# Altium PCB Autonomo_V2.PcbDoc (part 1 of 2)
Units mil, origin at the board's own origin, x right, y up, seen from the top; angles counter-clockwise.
Board outline 3937.01 x 3937.01 mil, 4 copper layers (Top Layer, GND, PWR, Bottom Layer), stack 62.204 mil thick; 148 components, 84 nets, 484 pads, 385 vias.
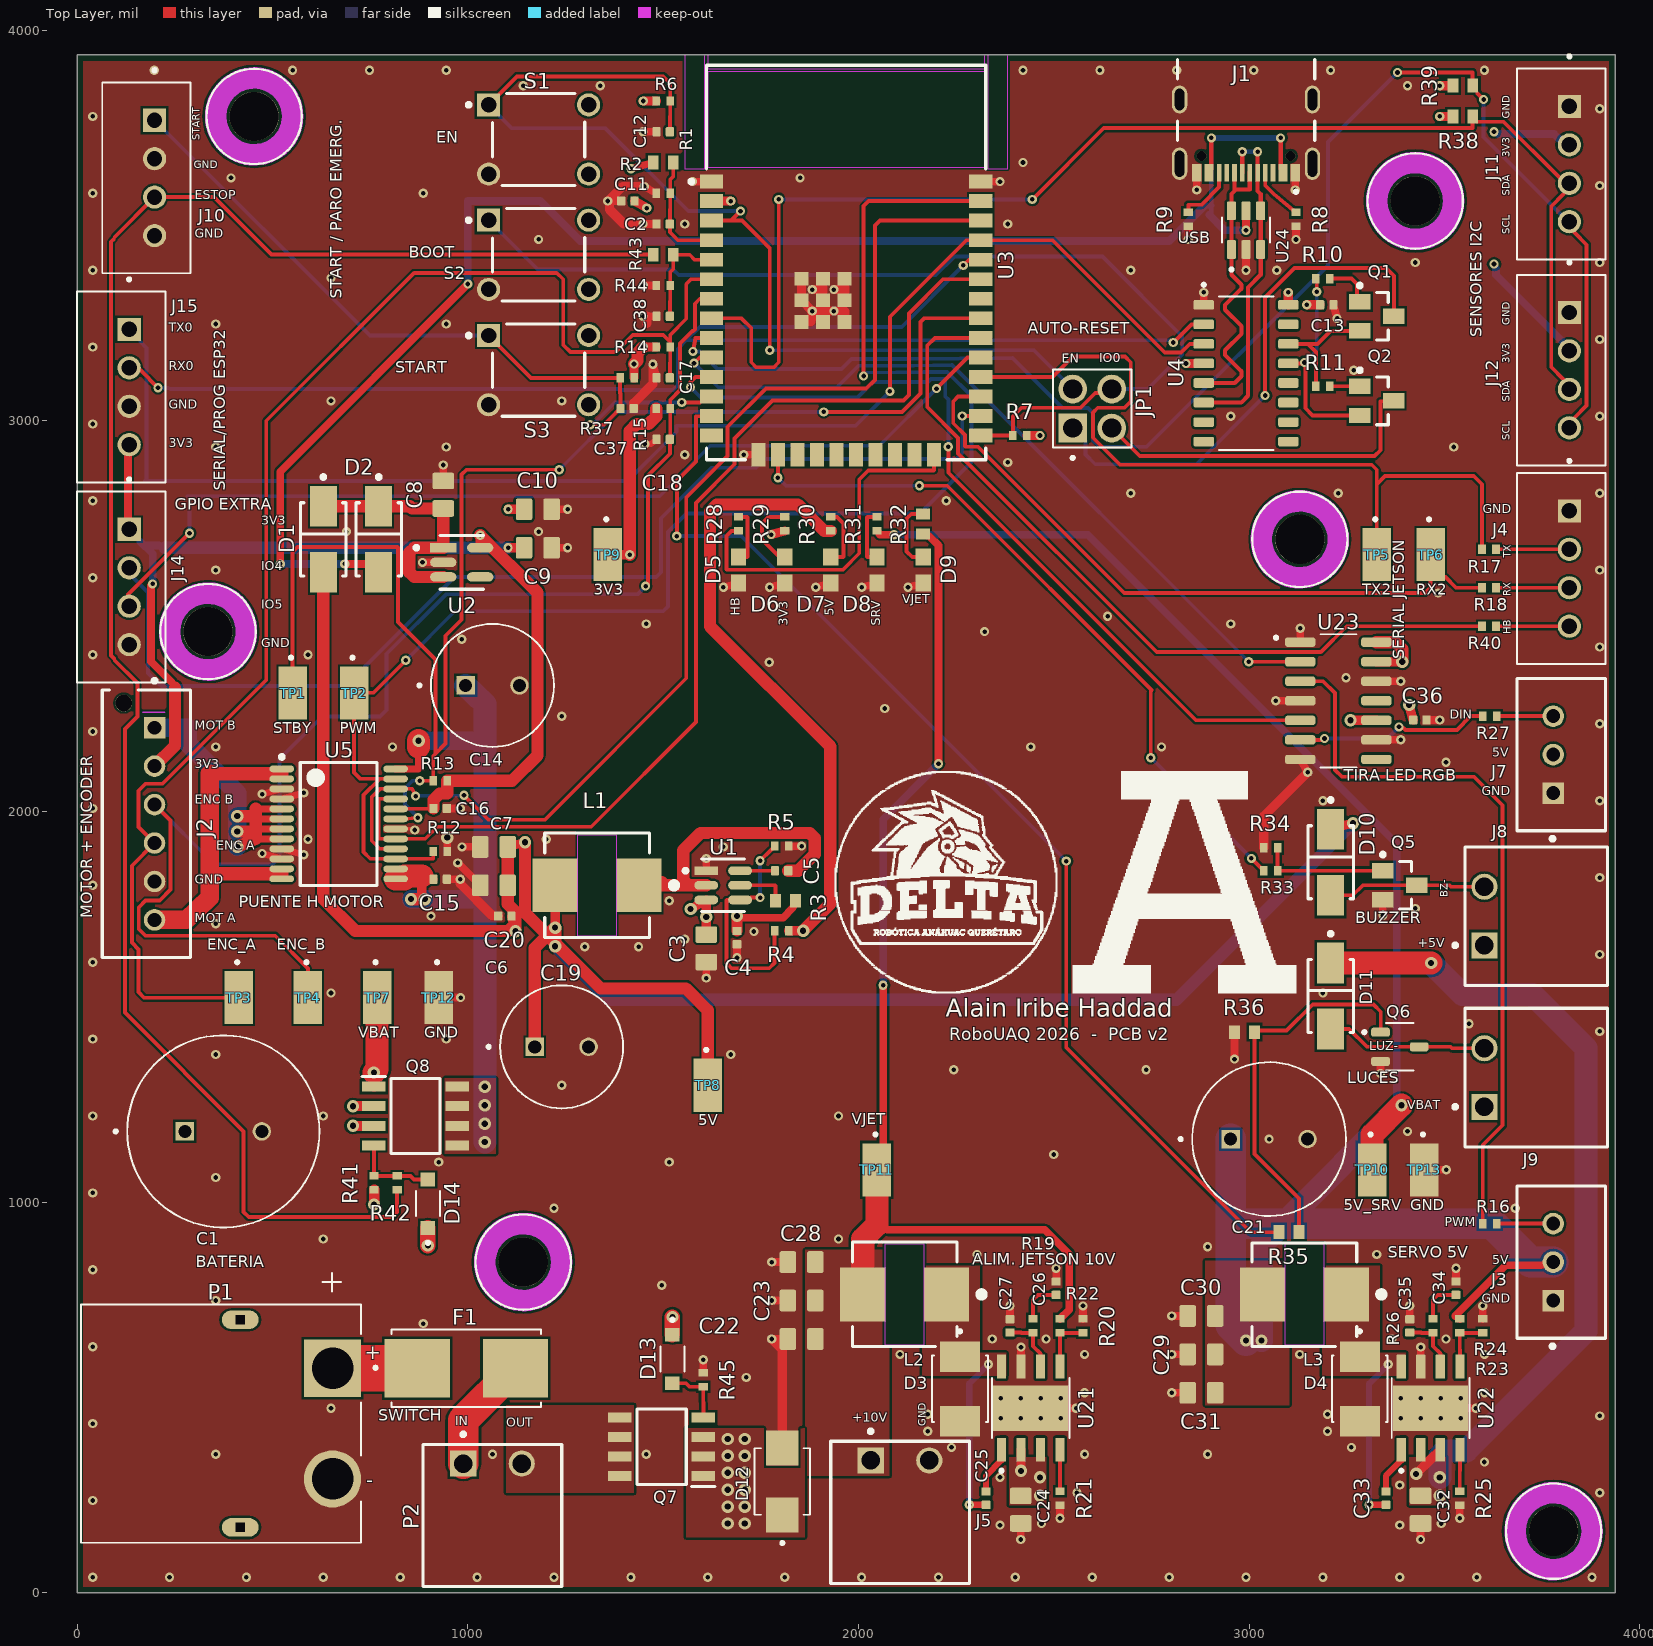
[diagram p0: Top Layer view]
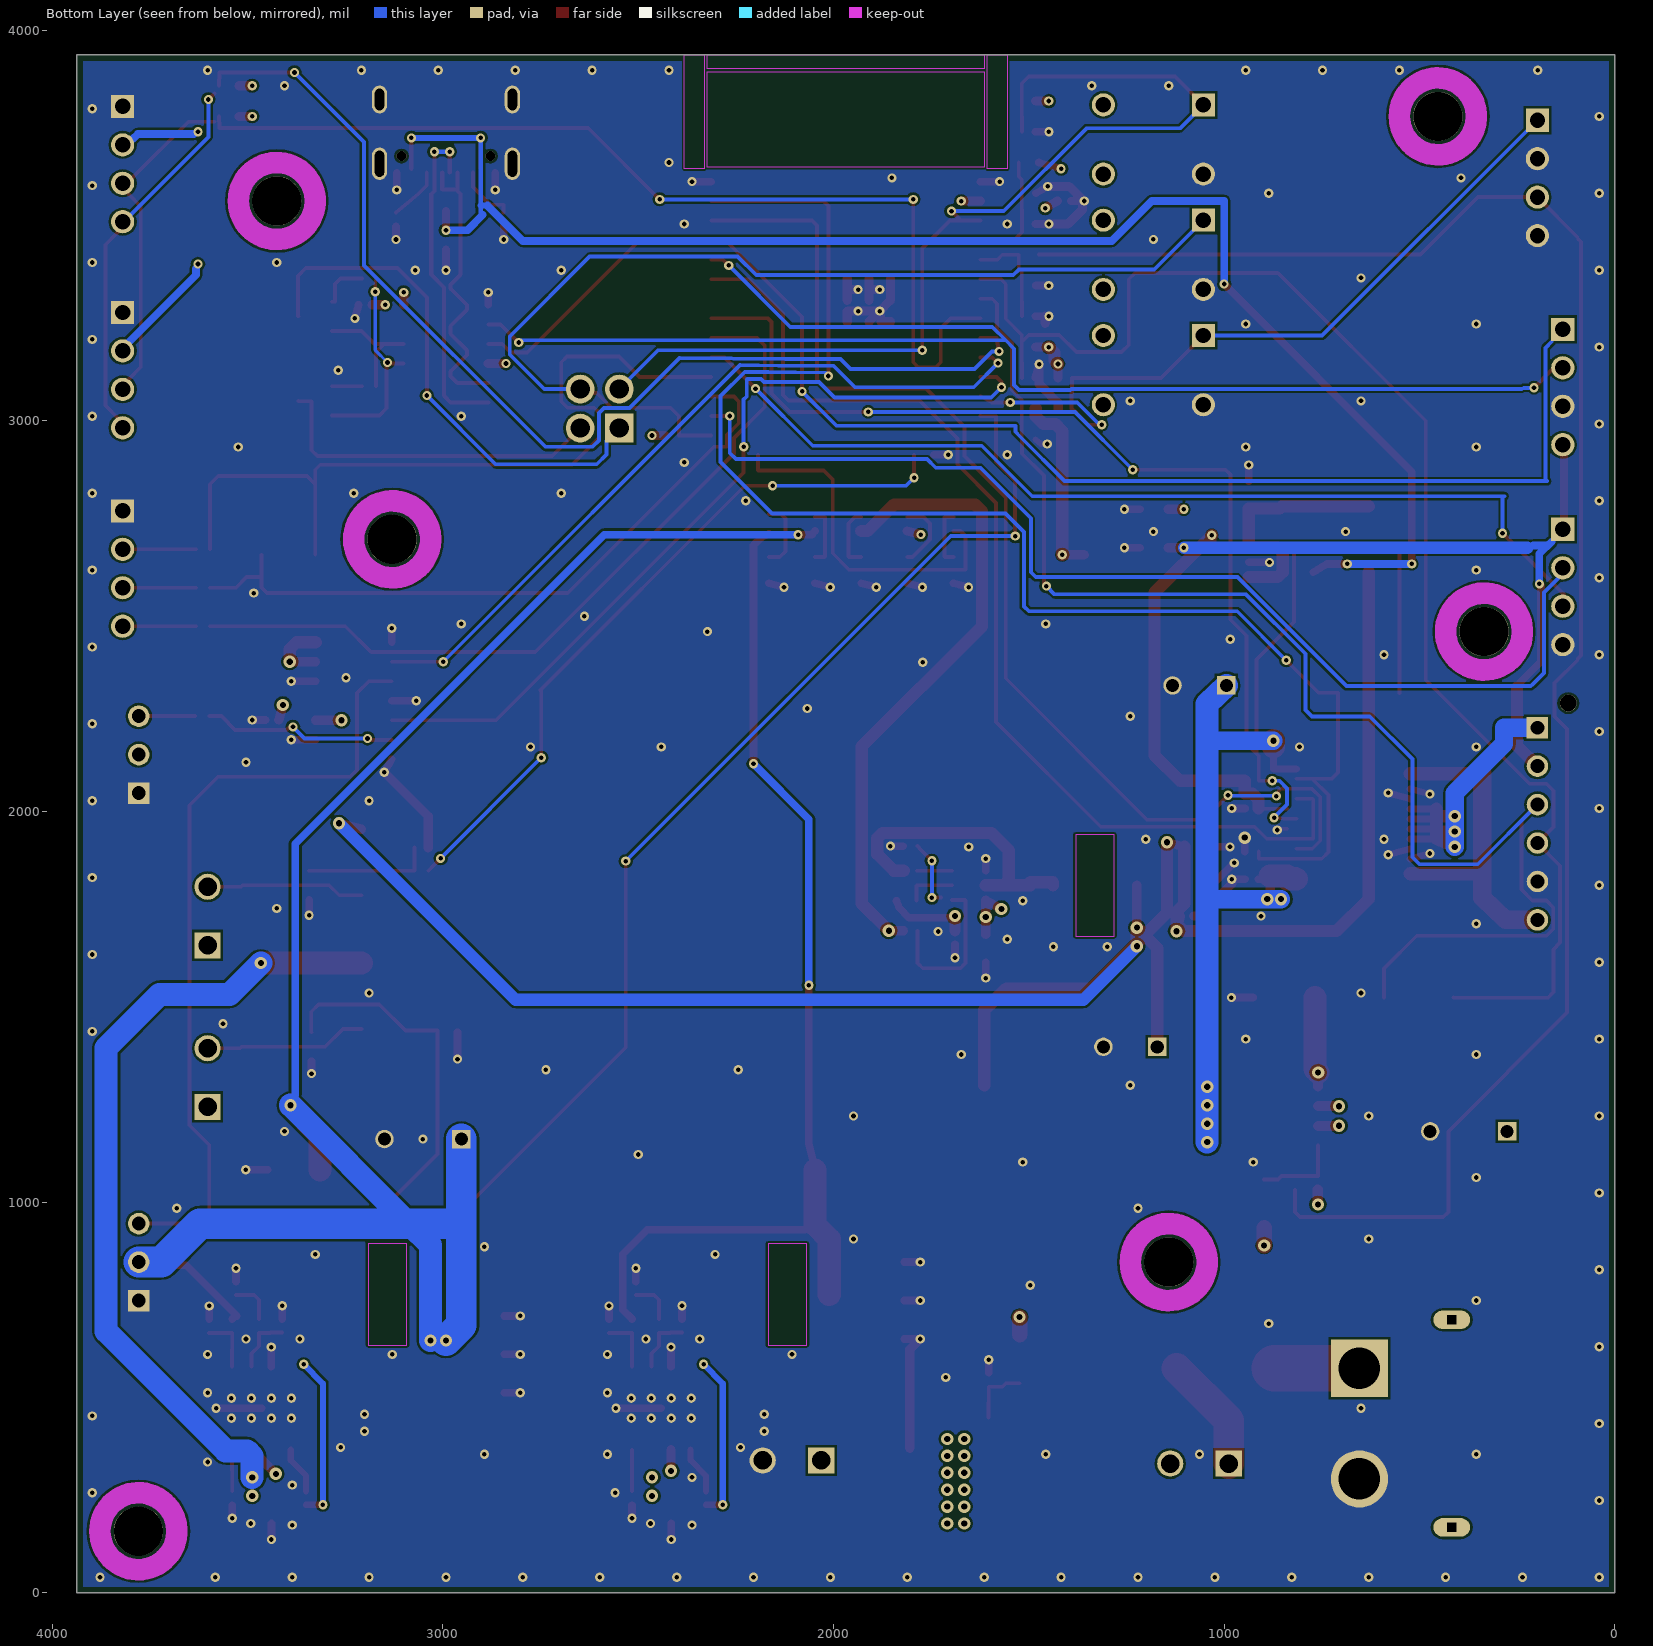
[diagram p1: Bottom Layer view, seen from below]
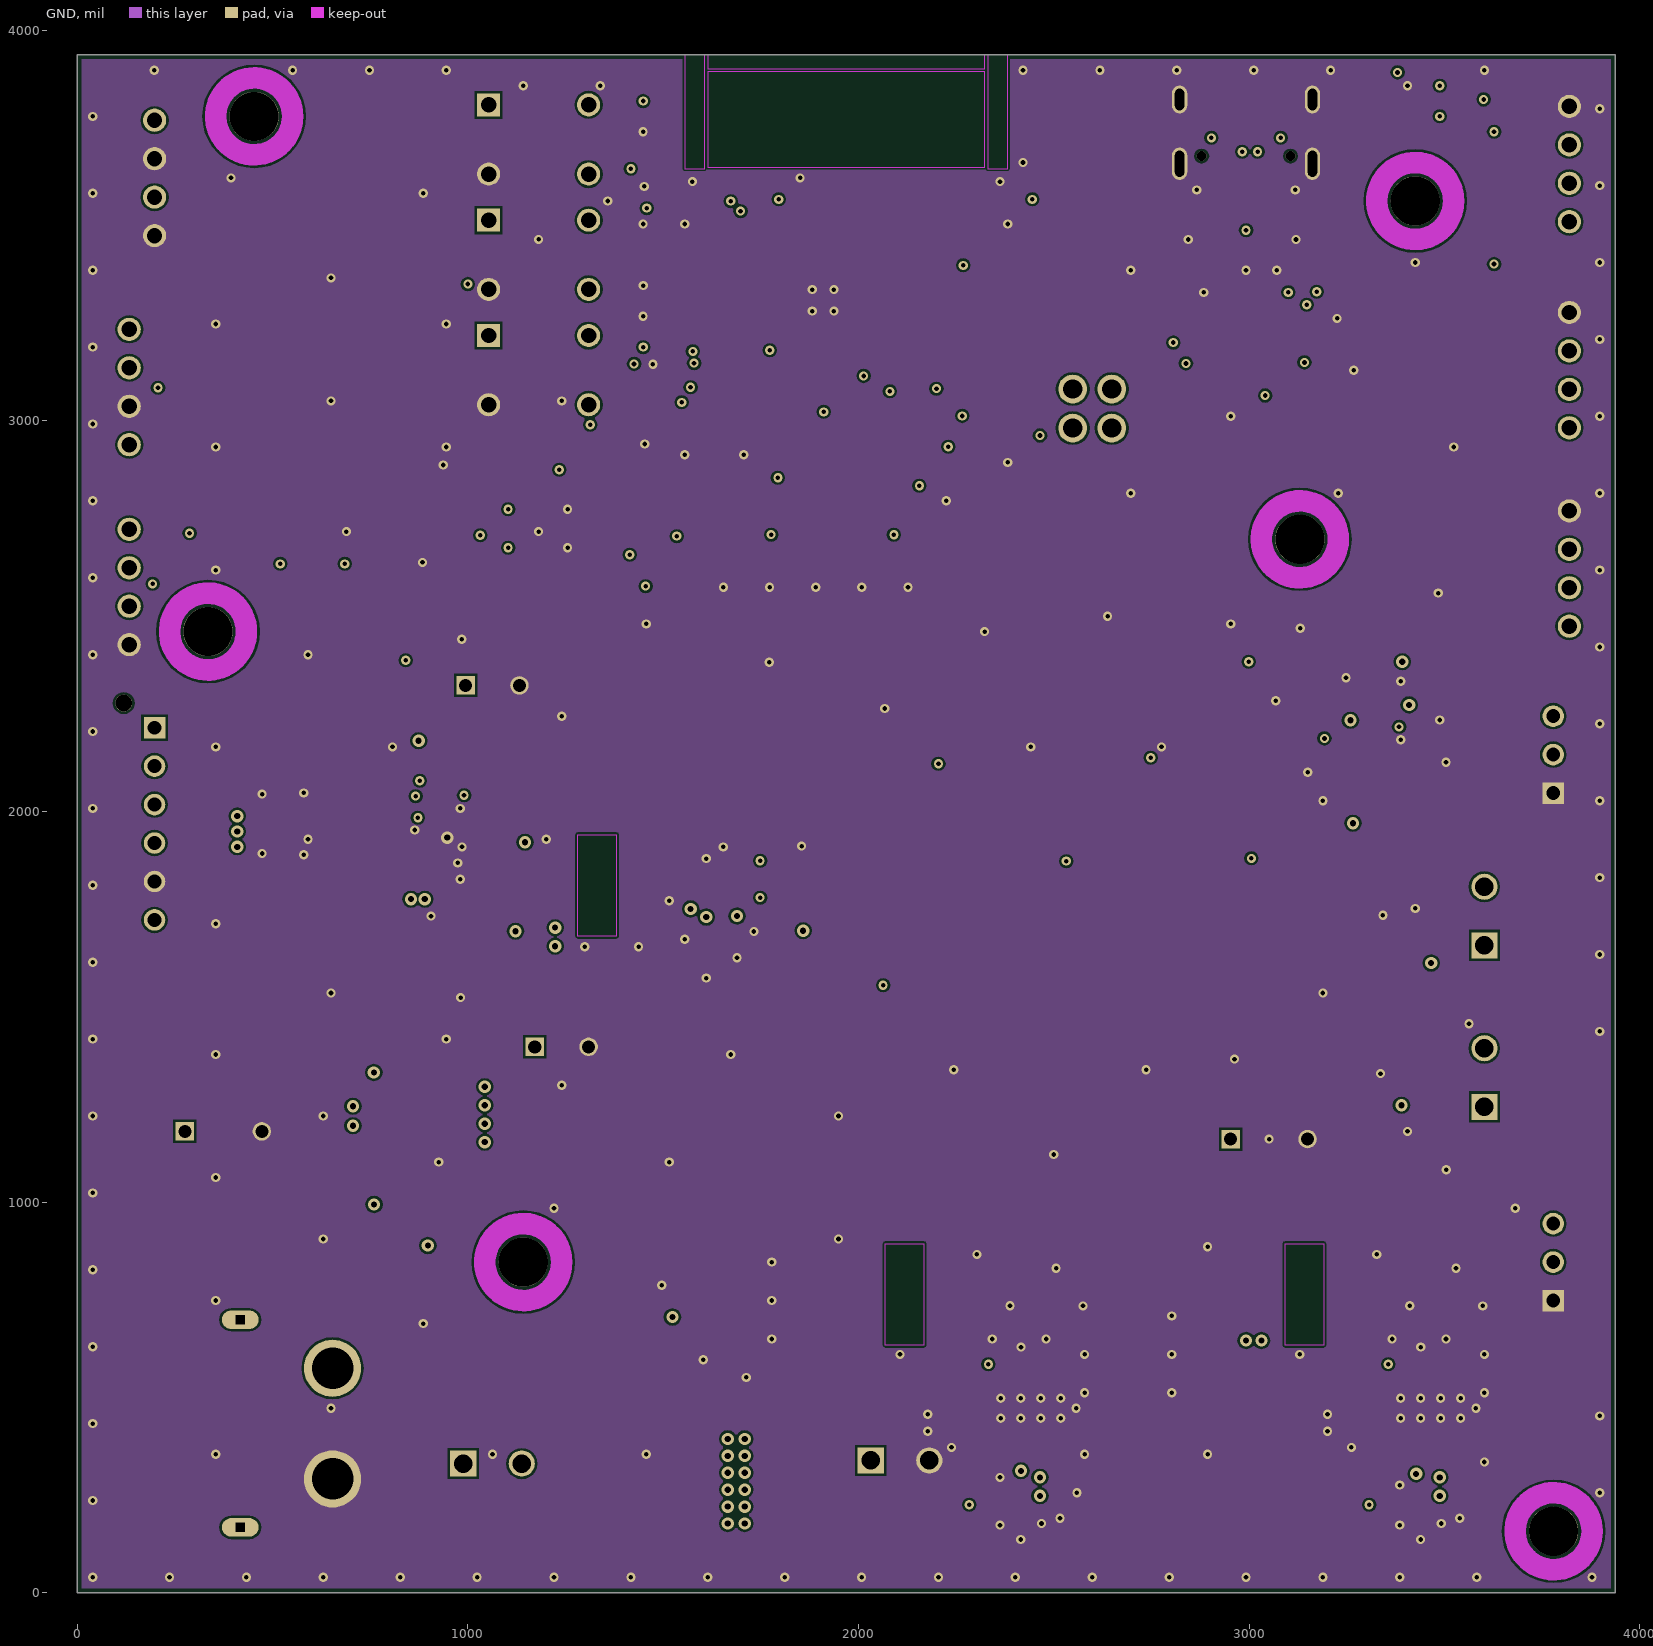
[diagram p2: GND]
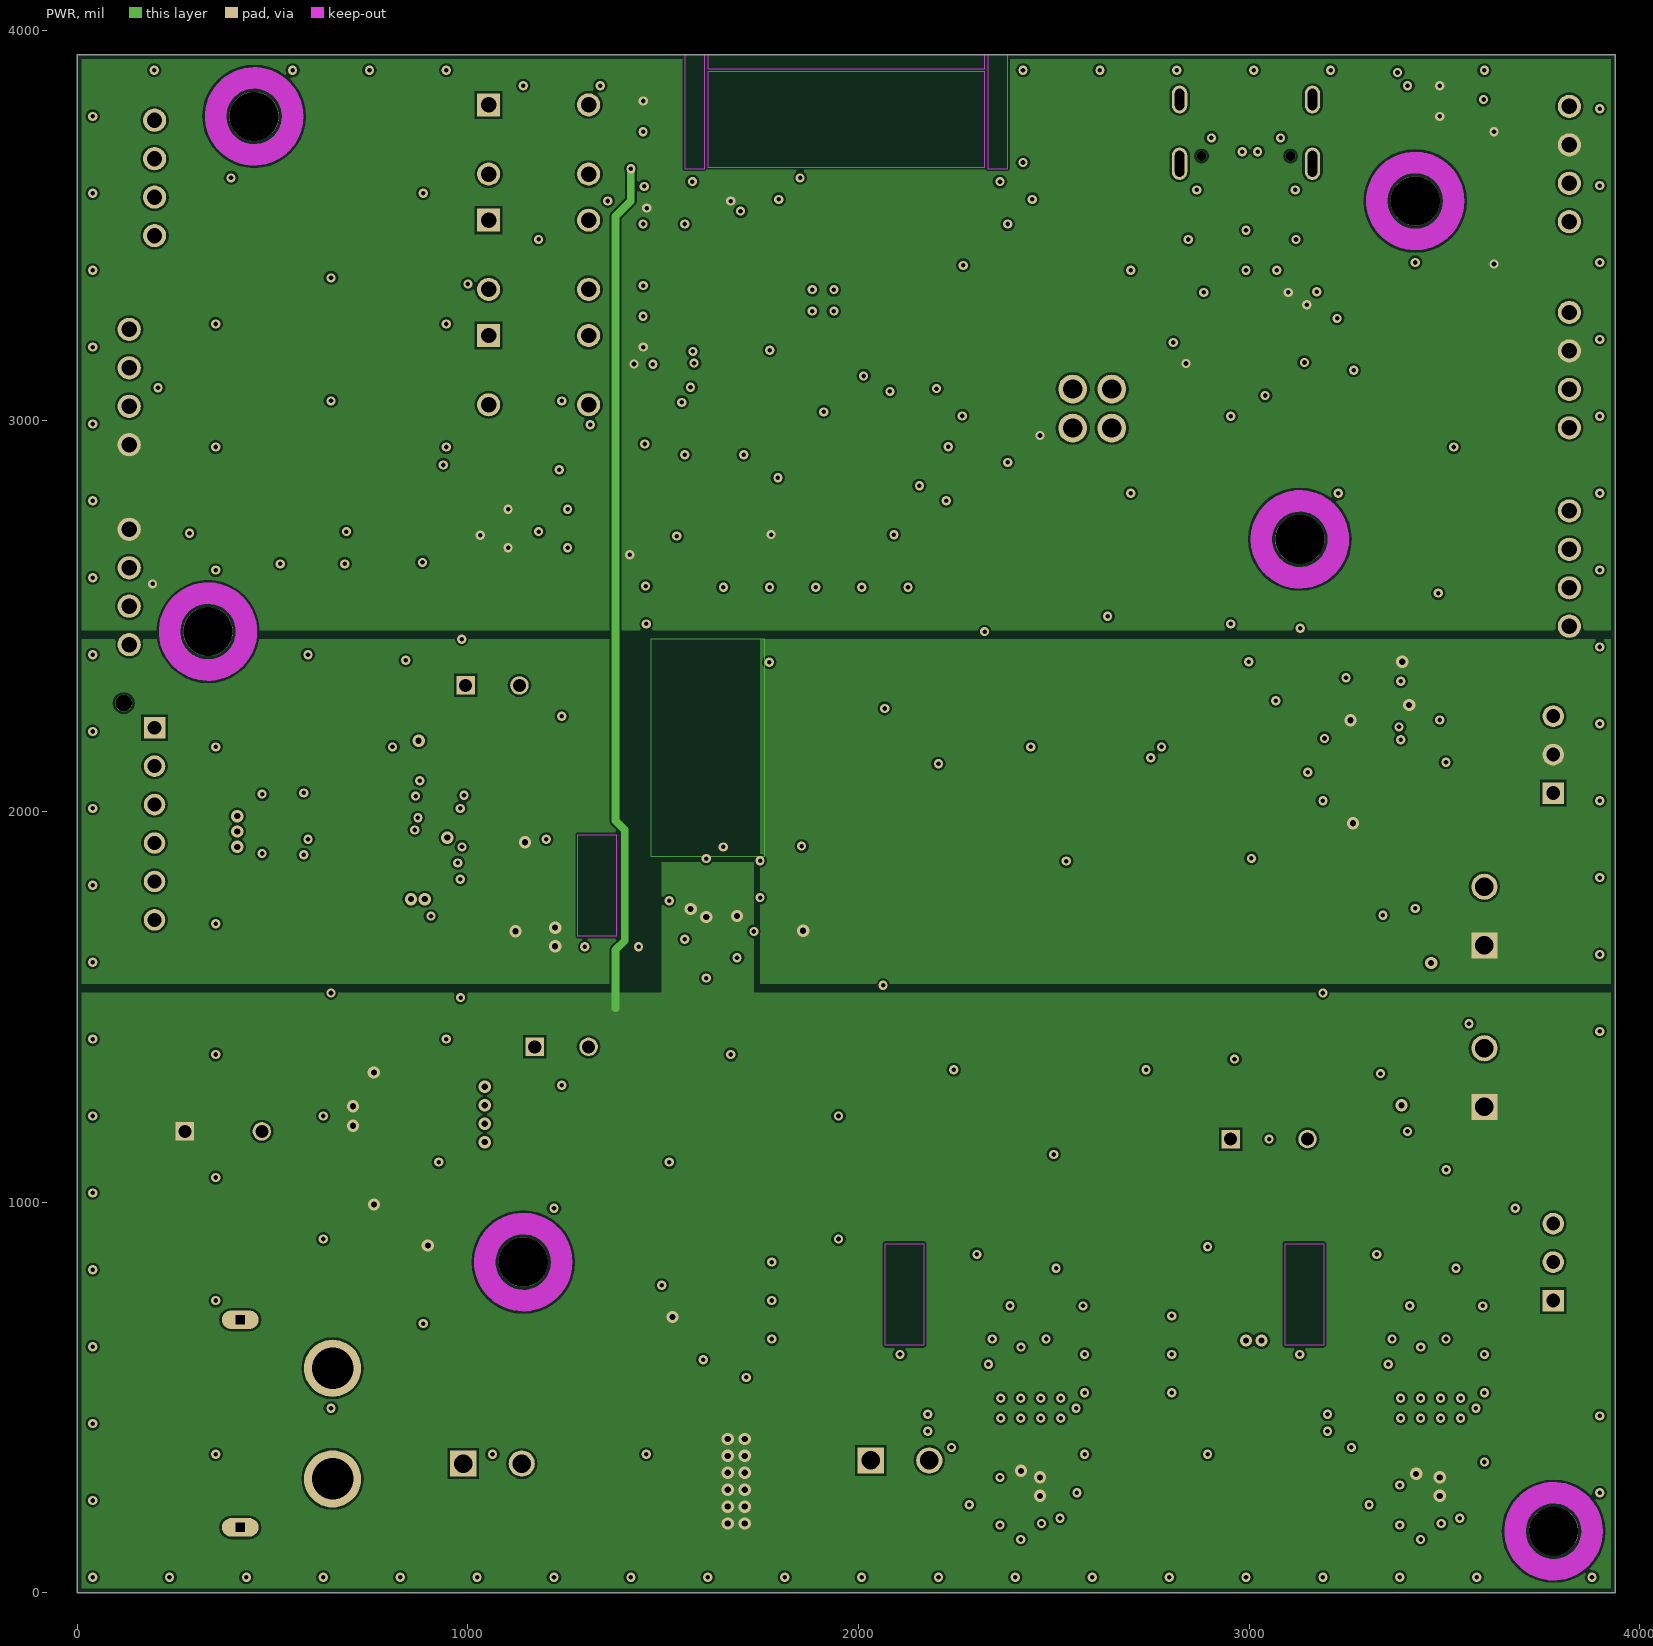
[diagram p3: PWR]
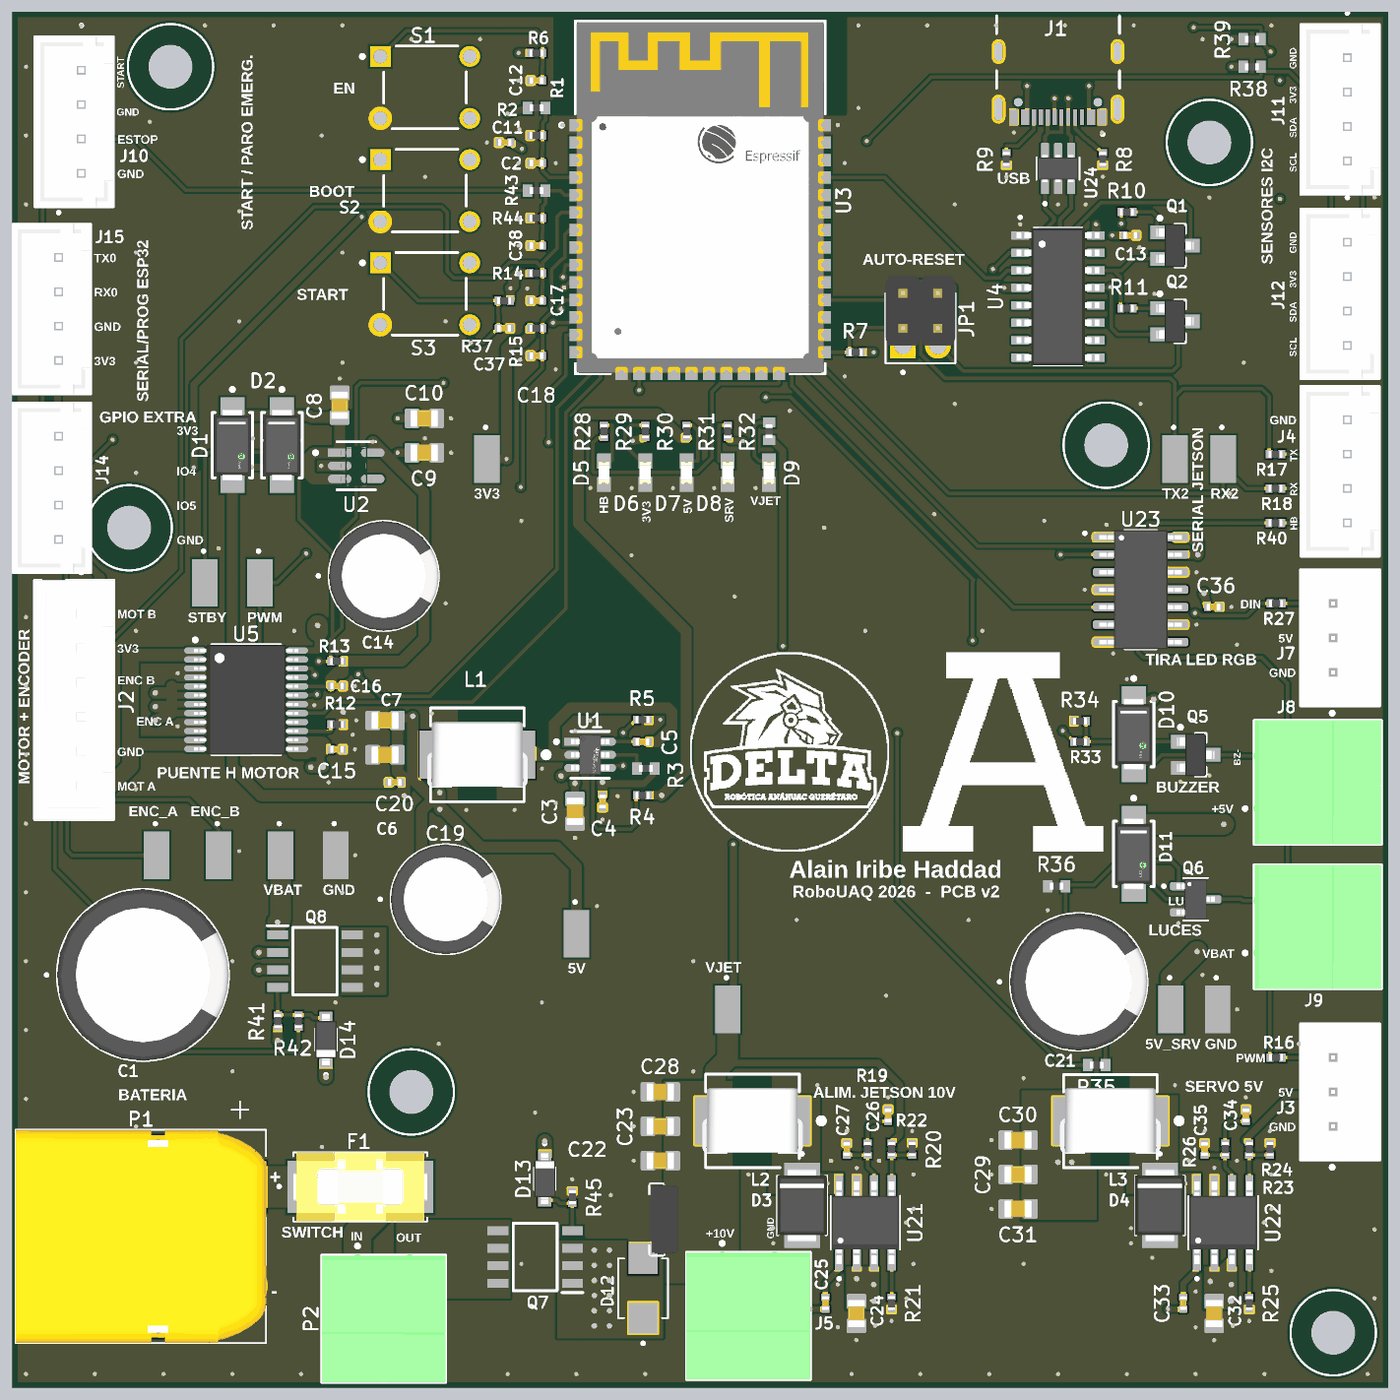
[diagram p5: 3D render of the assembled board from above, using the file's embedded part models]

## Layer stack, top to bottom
Top Solder: solder mask 0.4, Solder Resist, Dk 3.5
Top Layer: signal copper 1.4
Dielectric 2: prepreg 7.874, PP-006, Dk 4.1
GND: signal copper 1.378
Dielectric 1: dielectric 40.9, FR-4, Dk 4.8
PWR: signal copper 1.378
Dielectric 3: prepreg 7.874, PP-006, Dk 4.1
Bottom Layer: signal copper 1.4
Bottom Solder: solder mask 0.4, Solder Resist, Dk 3.5

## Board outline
0,0 0,3937.01 3937.01,3937.01 3937.01,0

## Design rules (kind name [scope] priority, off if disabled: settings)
Clearance C_NeckDown [(InRegionAbsolute(433,1760,906,2177) Or InRegionAbsolute(1520,1703,1787,1919) Or InRegionAbsolute(844,2529,1124,2746) Or InRegionAbsolute(2799,2876,3185,3369) Or InRegionAbsolute(2860,3380,3124,3596) Or InRegionAbsolute(2743,3552,3241,3917) Or InRegionAbsolute(3029,2059,3428,2508) Or InRegionAbsolute(2285,277,2596,669) Or InRegionAbsolute(3309,277,3620,669) Or InRegionAbsolute(1300,227,1692,521) Or InRegionAbsolute(670,1074,1062,1367) Or InRegionAbsolute(2264,197,2350,600) Or InRegionAbsolute(3287,197,3374,600))] p1: gap=5.91 ignorepadtopadclearanceinfootprint=FALSE
Clearance C_PowerHi [InNetClass('POWER_HI')] p2: gap=7.87 ignorepadtopadclearanceinfootprint=FALSE
Clearance [All] p3: gap=5.91 ignorepadtopadclearanceinfootprint=FALSE
DiffPairsRouting [All] p1: maxlimit=6 minlimit=5 mostfreqgap=6 toplayer_mingap=6 toplayer_minwidth=10.95 toplayer_maxwidth=10.95 toplayer_prefwidth=10.95 midlayer1_maxgap=5 midlayer1_prefgap=5 midlayer1_minwidth=4.33 midlayer1_maxwidth=4.33 midlayer1_prefwidth=4.33 midlayer2_maxgap=5 midlayer2_prefgap=5 midlayer2_minwidth=4.33 midlayer2_maxwidth=4.33 midlayer2_prefwidth=4.33 bottomlayer_mingap=6 bottomlayer_minwidth=10.95 bottomlayer_maxwidth=10.95 bottomlayer_prefwidth=10.95 impedanceprofiledriven=TRUE impedanceprofileid={DB9AC6A6-0DAB-40E2-92AF-4522C3993068} impedanceprofilevalue=90.000000 maxuncoupledlength=500
HoleSize [All] p1: absolutevalues=TRUE maxlimit=129.92 minlimit=1 maxpercent=80.000 minpercent=20.000
MinimumSolderMaskSliver Sliver_ESP_EP [InComponent('U3')] p1: minsoldermaskwidth=0
MinimumSolderMaskSliver [All] p2: minsoldermaskwidth=3
PolygonConnect [All] p1: connectstyle=Direct reliefconductorwidth=10 reliefentries=4 polygonreliefangle="90 Angle" airgapwidth=10
RoutingLayers [All] p1: top layer_v5=TRUE mid layer 1_v5=FALSE mid layer 2_v5=FALSE bottom layer_v5=TRUE
RoutingVias V_Power [InNetClass('POWER_HI') Or InNetClass('POWER') Or InNet('GND')] p1: holewidth=15.75 width=31.5 viastyle="Through Hole" minholewidth=11.81 minwidth=23.62 maxholewidth=19.68 maxwidth=39.37
RoutingVias [All] p2: holewidth=11.81 width=23.62 viastyle="Through Hole" minholewidth=11.81 minwidth=23.62 maxholewidth=15.75 maxwidth=31.5
SilkToSilkClearance [All] p1: silktosilkclearance=4
SilkToSolderMaskClearance [IsPad] p1: minsilkscreentomaskgap=4 clearancetoexposedcopper=TRUE
SolderMaskExpansion Tent_Vias [IsVia] p1: expansion=0 istentingtop=TRUE
SolderMaskExpansion [All] p2: expansion=0 istentingtop=FALSE
SupplyNets "Schematic Supply Nets_2" [InNet('+3V3')] p1: voltage=0.000
SupplyNets "Schematic Supply Nets_1" [InNet('+5V')] p2: voltage=0.000
SupplyNets "Schematic Supply Nets" [InNet('GND')] p3: voltage=0.000
Width W_NeckDown [(InRegionAbsolute(433,1760,906,2177) Or InRegionAbsolute(1520,1703,1787,1919) Or InRegionAbsolute(844,2529,1124,2746) Or InRegionAbsolute(2799,2876,3185,3369) Or InRegionAbsolute(2860,3380,3124,3596) Or InRegionAbsolute(2743,3552,3241,3917) Or InRegionAbsolute(3029,2059,3428,2508) Or InRegionAbsolute(2285,277,2596,669) Or InRegionAbsolute(3309,277,3620,669) Or InRegionAbsolute(1300,227,1692,521) Or InRegionAbsolute(670,1074,1062,1367) Or InRegionAbsolute(2264,197,2350,600) Or InRegionAbsolute(3287,197,3374,600))] p1: maxlimit=314.96 minlimit=7.87 preferedwidth=15.75
Width W_USB [InNetClass('USB')] p2: maxlimit=13.78 minlimit=7.87 preferedwidth=10.94
Width W_GND [InNet('GND')] p3: maxlimit=314.96 minlimit=11.81 preferedwidth=23.62
Width W_Power [InNetClass('POWER')] p4: maxlimit=236.22 minlimit=19.68 preferedwidth=31.5
Width W_PowerHi [InNetClass('POWER_HI')] p5: maxlimit=314.96 minlimit=19.68 preferedwidth=59.06
Width [All] p6: maxlimit=39.37 minlimit=5.91 preferedwidth=9.84
24 further rules are at their usual default settings.

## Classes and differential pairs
net class POWER_HI: +5V_SERVO +VJET MOT_A MOT_B NetF1_1 NetF1_2 SW_SERVO SW_VJET VBAT VBAT_MOT VBAT_SW
net class POWER: 5V_LOGIC +3V3 +5V SW VBUS
net class USB: USB_DN USB_DP

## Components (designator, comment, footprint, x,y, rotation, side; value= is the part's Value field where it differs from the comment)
C1 "EEUFR1H471" CAPPRD500W60D1250H2000 374.02,1181.1 r0 top
C2 "CL05B104KO5NNNC" CAPC1005X55N 1500,3503.94 r180 top
C3 "CL21A226MAQNNNE" CAPC2012X140N 1610.24,1649.61 r270 top
C4 "CL05B104KO5NNNC" CAPC1005X55N 1688.98,1677.17 r270 top
C5 "CL05B104KO5NNNC" CAPC1005X55N 1803.15,1848.43 r0 top
C6 "CL21A226MAQNNNE" CAPC2012X140N 1066.93,1811.02 r180 top
C7 "CL21A226MAQNNNE" CAPC2012X140N 1066.93,1909.45 r180 top
C8 "CL21A106KOQNNNE" CAPC2012X140N 937.01,2811.02 r90 top
C9 "CL21A106KOQNNNE" CAPC2012X140N 1179.13,2675.2 r0 top
C10 "CL21A226MAQNNNE" CAPC2012X140N 1179.13,2773.62 r0 top
C11 "CL05B104KO5NNNC" CAPC1005X55N 1409.45,3562.99 r180 top
C12 "CL05A105KA5NNNC" CAPC1005X55N 1500,3740.16 r180 top
C13 "CL05B104KO5NNNC" CAPC1005X55N 3198.82,3297.24 r0 top
C14 "EEUFR1H101" CAPPRD350W60D800H1150 1062.99,2322.83 r0 top
C15 "CL05B104KO5NNNC" CAPC1005X55N 929.13,1826.77 r0 top
C16 "CL05B104KO5NNNC" CAPC1005X55N 929.13,2007.87 r0 top
C17 "CL05B102KB5NNNC" CAPC1005X55N 1500,3110.24 r180 top
C18 "CL05B102KB5NNNC" CAPC1005X55N 1500,2952.76 r180 top
C19 "EEUFR1C471" CAPPRD350W60D800H1150 1240.16,1397.64 r0 top
C20 "CL05B104KO5NNNC" CAPC1005X55N 1094.49,1732.28 r180 top
C21 "EEUFR1C102" CAPPRD500W60D1000H1600 3051.18,1161.42 r0 top
C22 "CL21A226MAQNNNE" CAPC2012X140N 1854.33,649.61 r180 top
C23 "CL21A226MAQNNNE" CAPC2012X140N 1854.33,748.03 r180 top
C24 "CL21A106KOQNNNE" CAPC2012X140N 2415.35,212.6 r270 top
C25 "CL05B104KO5NNNC" CAPC1005X55N 2326.77,242.13 r270 top
C26 "CL05B472KB5NNNC" CAPC1005X55N 2505.91,779.53 r90 top
C27 "CL05C820JB5NNNC" CAPC1005X55N 2387.8,683.07 r90 top
C28 "CL21A226MAQNNNE" CAPC2012X140N 1854.33,846.46 r180 top
C29 "CL21A226MAQNNNE" CAPC2012X140N 2877.95,610.24 r180 top
C30 "CL21A226MAQNNNE" CAPC2012X140N 2877.95,708.66 r180 top
C31 "CL21A226MAQNNNE" CAPC2012X140N 2877.95,511.81 r180 top
C32 "CL21A106KOQNNNE" CAPC2012X140N 3438.98,212.6 r270 top
C33 "CL05B104KO5NNNC" CAPC1005X55N 3350.39,242.13 r270 top
C34 "CL05B472KB5NNNC" CAPC1005X55N 3529.53,779.53 r90 top
C35 "CL05C820JB5NNNC" CAPC1005X55N 3411.42,683.07 r90 top
C36 "CL05B104KO5NNNC" CAPC1005X55N 3437.01,2234.25 r0 top
C37 "CL05B104KO5NNNC" CAPC1005X55N 1407.48,3031.5 r0 top
C38 "CL05B104KO5NNNC" CAPC1005X55N 1500,3267.72 r180 top
D1 "SS14" FP-403AE-MFG 629.92,2696.85 r90 top
D2 "SS14" FP-403AE-MFG 771.65,2696.85 r90 top
D3 "SK56B" DIO_SK56B 2259.84,521.65 r270 top
D4 "SK56B" DIO_SK56B 3283.46,521.65 r270 top
D5 "LTST-C191KGKT" 0603 1692.91,2618.11 r90 top
D6 "LTST-C191KGKT" 0603 1811.02,2618.11 r90 top
D7 "LTST-C191KGKT" 0603 1929.13,2618.11 r90 top
D8 "LTST-C191KGKT" 0603 2047.24,2618.11 r90 top
D9 "LTST-C191KGKT" 0603 2165.35,2618.11 r90 top
D10 "SS14" FP-403AE-MFG 3208.66,1870.08 r90 top
D11 "SS14" FP-403AE-MFG 3208.66,1527.56 r90 top
D12 "SMBJ15A" DIOM4336X265N 1805,284.76 r90 top
D13 "BZT52C12-7-F" DIO_BZT52C12-7-F 1523.62,598.43 r270 top
D14 "BZT52C12-7-F" DIO_BZT52C12-7-F 897.64,996.06 r90 top
F1 "0154010.DRL" FUSE_0154010.DRL 996.06,574.8 r0 top
J1 "USB4105-GF-A" GCT_USB4105-GF-A 2992.13,3822.83 r180 top
J2 "B6B-XH-AM(LF)(SN)" FP-B6B-XH-AM_LF_SN-MFG 177.17,1968.5 r90 top
J3 "B3B-XH-A(LF)(SN)" FP-B3B-XH-A_LF_SN-MFG 3799.21,846.46 r90 top
J4 "B4B-XH-A(LF)(SN)" JST_B4B-XH-A(LF)(SN) 3799.21,2622.05 r90 top
J5 "1803277" PHOE-1803277_V 2106.3,338.58 r0 top
J7 "B3B-XH-A(LF)(SN)" FP-B3B-XH-A_LF_SN-MFG 3799.21,2145.67 r90 top
J8 "1803277" PHOE-1803277_V 3602.36,1732.28 r90 top
J9 "1803277" PHOE-1803277_V 3602.36,1318.9 r90 top
J10 "B4B-XH-A(LF)(SN)" JST_B4B-XH-A(LF)(SN) 177.17,3622.05 r90 top
J11 "B4B-XH-A(LF)(SN)" JST_B4B-XH-A(LF)(SN) 3799.21,3657.48 r90 top
J12 "B4B-XH-A(LF)(SN)" JST_B4B-XH-A(LF)(SN) 3799.21,3129.92 r90 top
J14 "B4B-XH-A(LF)(SN)" JST_B4B-XH-A(LF)(SN) 112.2,2574.8 r90 top
J15 "B4B-XH-A(LF)(SN)" JST_B4B-XH-A(LF)(SN) 112.2,3086.61 r90 top
JP1 "61300421121" WURTH_61300421121 2598.43,3031.5 r0 top
L1 "WE-LHMI_7050" WE-LHMI_7050 1330.71,1811.02 r180 top
L2 "WE-LHMI_7050" WE-LHMI_7050 2118.11,763.78 r180 top
L3 "WE-LHMI_7050" WE-LHMI_7050 3141.73,763.78 r180 top
P1 "XT60PW-M" AMASS_XT60PW-M 417.32,433.07 r270 top
P2 "1803277" PHOE-1803277_V 1062.99,330.71 r0 top
Q1 "MMBT3904" FAIR-SOT23-3_V 3326.77,3267.72 r0 top
Q2 "MMBT3904" FAIR-SOT23-3_V 3326.77,3051.18 r0 top
Q5 "MMBT3904" FAIR-SOT23-3_V 3385.83,1811.02 r0 top
Q6 "AO3400A" SOT95P280X125-3N 3385.83,1397.64 r0 top
Q7 "AO4407A" SOIC127P600X175-8N 1496.06,374.02 r180 top
Q8 "AO4407A" SOIC127P600X175-8N 866.14,1220.47 r0 top
R1 "RC0402FR-07100KL" RESC1005X40 1500,3661.42 r0 top
R2 "RC0402FR-0722KL" RESC1005X40N 1500,3582.68 r180 top
R3 "RC0402FR-07100KL" RESC1005X40 1812.99,1771.65 r180 top
R4 "RC0402FR-0754K9L" RESC1005X40N 1803.15,1694.88 r180 top
R5 "RC0402FR-0710KL" RESC1005X40N 1803.15,1911.42 r0 top
R6 "RC0402FR-0710KL" RESC1005X40N 1500,3818.9 r0 top
R7 "RC0402FR-0710KL" RESC1005X40N 2413.39,2962.6 r180 top
R8 "RC0402FR-075K1L" RESC1005X40N 3120.08,3515.75 r270 top
R9 "RC0402FR-075K1L" RESC1005X40N 2844.49,3515.75 r270 top
R10 "RC0402FR-0710KL" RESC1005X40N 3188.98,3364.17 r0 top
R11 "RC0402FR-0710KL" RESC1005X40N 3188.98,3088.58 r0 top
R12 "RC0402FR-0710KL" RESC1005X40N 929.13,1897.64 r0 top
R13 "RC0402FR-0710KL" RESC1005X40N 929.13,2078.74 r180 top
R14 "RC0402FR-0710KL" RESC1005X40N 1500,3188.98 r0 top
R15 "RC0402FR-0710KL" RESC1005X40N 1500,3031.5 r0 top
R16 "RC0402FR-07220RL" RESC1005X40N 3616.14,944.88 r180 top
R17 "RC0402FR-07330RL" RESC1005X40N 3614.17,2671.26 r180 top
R18 "RC0402FR-07330RL" RESC1005X40N 3614.17,2572.83 r180 top
R19 "RC0402FR-07115KL" RESC1005X40N 2515.75,683.07 r270 top
R20 "RC0402FR-0710KL" RESC1005X40N 2574.8,683.07 r90 top
R21 "RC0402FR-07200KL" RESC1005X40N 2515.75,242.13 r270 top
R22 "RC0402FR-078K2L" RESC1005X40N 2446.85,683.07 r90 top
R23 "RC0402FR-0754K9L" RESC1005X40N 3539.37,683.07 r270 top
R24 "RC0402FR-0710KL" RESC1005X40N 3598.43,683.07 r90 top
R25 "RC0402FR-07200KL" RESC1005X40N 3539.37,242.13 r270 top
R26 "RC0402FR-078K2L" RESC1005X40N 3470.47,683.07 r90 top
R27 "RC0402FR-07330RL" RESC1005X40N 3616.14,2244.09 r0 top
R28 "RC0402FR-071KL" RESC1005X40N 1692.91,2736.22 r90 top
R29 "RC0402FR-071KL" RESC1005X40N 1811.02,2736.22 r90 top
R30 "RC0402FR-071KL" RESC1005X40N 1929.13,2736.22 r90 top
R31 "RC0402FR-071KL" RESC1005X40N 2047.24,2736.22 r90 top
R32 "RC0402FR-074K7L" RESC1005X40 2165.35,2736.22 r90 top
R33 "RC0402FR-071KL" RESC1005X40N 3055.12,1848.43 r0 top
R34 "RC0402FR-0710KL" RESC1005X40N 3055.12,1907.48 r180 top
R35 "RC0402FR-07100RL" RESC1005X40 3102.36,923.23 r0 top
R36 "RC0402FR-07100KL" RESC1005X40 2988.19,1435.04 r180 top
R37 "RC0402FR-0710KL" RESC1005X40N 1407.48,3110.24 r180 top
R38 "RC0402FR-074K7L" RESC1005X40 3547.24,3779.53 r0 top
R39 "RC0402FR-074K7L" RESC1005X40 3547.24,3858.27 r0 top
R40 "RC0402FR-07330RL" RESC1005X40N 3614.17,2474.41 r180 top
R41 "RC0402FR-0710KL" RESC1005X40N 759.84,1049.21 r90 top
R42 "RC0402FR-071KL" RESC1005X40N 818.9,1049.21 r270 top
R43 "RC0402FR-07100KL" RESC1005X40 1500,3425.2 r0 top
R44 "RC0402FR-0722KL" RESC1005X40N 1500,3346.46 r180 top
R45 "RC0402FR-0710KL" RESC1005X40N 1602.36,545.28 r90 top
S1 "B3F-1000" OMRON-B3F-1000-4_V 1181.1,3720.47 r0 top
S2 "B3F-1000" OMRON-B3F-1000-4_V 1181.1,3425.2 r0 top
S3 "B3F-1000" OMRON-B3F-1000-4_V 1181.1,3129.92 r0 top
TP1 "S1751-46R" S175146R 551.18,2303.15 r90 top
TP2 "S1751-46R" S175146R 708.66,2303.15 r90 top
TP3 "S1751-46R" S175146R 413.39,1523.62 r90 top
TP4 "S1751-46R" S175146R 590.55,1523.62 r90 top
TP5 "S1751-46R" S175146R 3326.77,2657.48 r90 top
TP6 "S1751-46R" S175146R 3464.57,2657.48 r90 top
TP7 "S1751-46R" S175146R 767.72,1523.62 r90 top
TP8 "S1751-46R" S175146R 1614.17,1299.21 r90 top
TP9 "S1751-46R" S175146R 1358.27,2657.48 r90 top
TP10 "S1751-46R" S175146R 3314.96,1082.68 r90 top
TP11 "S1751-46R" S175146R 2047.24,1082.68 r90 top
TP12 "S1751-46R" S175146R 925.2,1523.62 r90 top
TP13 "S1751-46R" S175146R 3448.82,1082.68 r90 top
U1 "TPS565201DDCT" FP-DDC0006A-IPC_B 1653.54,1811.02 r0 top
U2 "AP2112K-3.3TRG1" FP-SOT25-IPC_A 984.25,2637.8 r0 top
U3 "ESP32-WROOM-32E (4MB)" FP-ESP32-WROOM-32E_4MB-MFG 1968.5,3405.51 r0 top
U4 "CH340C" SOIC127P600X180-16N 2992.13,3122.05 r0 top
U5 "TB6612FNG" TOSH-SSOP-24_M 669.29,1968.5 r0 top
U21 "TPS54560BDDAR" VREG_LM5017MR/NOPB 2440.94,472.44 r90 top
U22 "TPS54560BDDAR" VREG_LM5017MR/NOPB 3464.57,472.44 r90 top
U23 "SN74AHCT125DR" SOIC127P600X175-14N 3228.35,2283.46 r0 top
U24 "USBLC6-2SC6" SOT95P280X145-6N 2992.13,3488.19 r90 top

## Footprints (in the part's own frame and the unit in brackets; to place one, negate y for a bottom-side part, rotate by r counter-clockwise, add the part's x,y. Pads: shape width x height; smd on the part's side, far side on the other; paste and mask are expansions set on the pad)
0603 [mm]
  rect 1.1x1 smd: 1(-0.85,0) 2(0.85,0)
  body extent -0.8,-0.4 0.8,0.4, height 0.55
AMASS_XT60PW-M [mm]
  rect 3.716x3.716 / inner round 3.716 / far side rect 3.716x3.716 hole 2.7 mask+0.102: 1(-3.6,6)
  round 3.716 hole 2.7 mask+0.102: 2(3.6,6)
  oval 1.2x2.4 hole 0.6 square mask+0.102: SH1(-6.75,0) SH2(6.75,0)
  silkscreen extent -9.8,-10.35 7.75,7.85, body extent -7.75,-10.35 7.75,7.85, height 8.4
CAPC1005X55N [mm]
  rrect25% 0.54x0.6 smd paste+0 mask+0.102: 1(-0.432,0) 2(0.432,0)
  body extent -0.5,-0.25 0.5,0.25, height 0.55
CAPC2012X140N [mm]
  rrect25% 1.08x1.42 smd: 1(-0.895,0) 2(0.895,0)
  body extent -1,-0.63 1,0.63, height 1.4
CAPPRD350W60D800H1150 [mm]
  round 1.2 hole 0.85: N(1.75,0)
  rect 1.2x1.2 hole 0.85: P(-1.75,0)
  silkscreen extent -4.85,-4 4,4, body extent -4,-4 4,4, height 11.5
CAPPRD500W60D1000H1600 [mm]
  round 1.2 hole 0.85: N(2.5,0)
  rect 1.2x1.2 hole 0.85: P(-2.5,0)
  silkscreen extent -5.85,-5 5,5, body extent -5,-5 5,5, height 16
CAPPRD500W60D1250H2000 [mm]
  round 1.2 hole 0.85: N(2.5,0)
  rect 1.2x1.2 hole 0.85: P(-2.5,0)
  silkscreen extent -7.1,-6.25 6.25,6.25, body extent -6.25,-6.25 6.25,6.25, height 20
DIO_BZT52C12-7-F [mm]
  rect 0.9x0.95 smd paste+0 mask+0.102: 1(-1.575,0) 2(1.575,0)
  silkscreen extent -2.65,-0.78 0.81,0.78, body extent -1.85,-0.77 1.85,0.77, height 1.35
DIO_SK56B [mm]
  rect 2x2.6 smd: A(2.1,0) C(-2.1,0)
  silkscreen extent -3.85,-1.81 2.16,1.81, body extent -2.68,-1.81 2.68,1.81, height 2.65
DIOM4336X265N [mm]
  rect 2.28x2.12 smd paste+0 mask+0.102: A(2.165,0) C(-2.165,0)
  silkscreen extent -4.1,-1.81 2.16,1.81, body extent 2.3,-2.58 7.7,-0.38, height 2.25
FAIR-SOT23-3_V [mm] "SOT23, 3-Leads, Body 3.12x1.5mm, Pitch 0.95mm"
  rect 1.4x1 smd: 1(-1.1,0.95) 2(-1.1,-0.95) 3(1.1,0)
  silkscreen extent -1.22,-1.55 0.75,2.12, body extent -1.35,-1.56 1.35,1.56, height 1.2
FP-403AE-MFG [mm]
  rect 2.65x1.75 smd paste+0 mask+0: 1(-2.15,0) 2(2.15,0)
  silkscreen extent -2.38,-1.47 4.17,1.48, body extent -3.57,-1.58 3.57,1.58, height 0.25
FP-B3B-XH-A_LF_SN-MFG [mm]
  rect 1.4x1.4 hole 0.9 paste-2539.97 mask+0: 1(-2.5,0.525)
  round 1.4 hole 0.9 paste-2539.97 mask+0: 2(0,0.525) 3(2.5,0.525)
  silkscreen extent -5.6,-2.88 4.95,2.87, body extent -5.05,-2.98 5.05,2.98, height 0.25
FP-B6B-XH-AM_LF_SN-MFG [mm]
  rect 1.4x1.4 hole 0.9 paste-2539.97 mask+0: 1(6.25,-0.525)
  round 1.4 hole 0.9 paste-2539.97 mask+0: 2(3.75,-0.525) 3(1.25,-0.525) 4(-1.25,-0.525) 5(-3.75,-0.525) 6(-6.25,-0.525)
  round 1.1 hole 1.1 unplated paste-2539.97 mask+0: ""(7.85,1.475)
  silkscreen extent -8.7,-2.87 9.42,2.88, body extent -8.8,-2.98 8.8,2.98, height 0.25
FP-DDC0006A-IPC_B [mm]
  rect 1.554x0.572 smd paste+0 mask+0: 1(-1.1,0.95)
  rrect100% 1.554x0.572 smd paste+0 mask+0: 2(-1.1,0) 3(-1.1,-0.95) 4(1.1,-0.95) 5(1.1,0) 6(1.1,0.95)
  silkscreen extent -2.57,-1.7 1.4,1.7, body extent -2.13,-1.7 2.13,1.7, height 0.25
FP-ESP32-WROOM-32E_4MB-MFG [mm]
  rect 1.5x0.9 smd paste+0 mask+0: 1(-8.75,5.26) 2(-8.75,3.99) 3(-8.75,2.72) 4(-8.75,1.45) 5(-8.75,0.18) 6(-8.75,-1.09) 7(-8.75,-2.36) 8(-8.75,-3.63) 9(-8.75,-4.9) 10(-8.75,-6.17) 11(-8.75,-7.44) 12(-8.75,-8.71) 13(-8.75,-9.98) 14(-8.75,-11.25) 25(8.75,-11.25) 26(8.75,-9.98) 27(8.75,-8.71) 28(8.75,-7.44) 29(8.75,-6.17) 30(8.75,-4.9) 31(8.75,-3.63) 32(8.75,-2.36) 33(8.75,-1.09) 34(8.75,0.18) 35(8.75,1.45) 36(8.75,2.72) 37(8.75,3.99) 38(8.75,5.26)
  rect 0.9x1.5 smd paste+0 mask+0: 15(-5.71,-12.5) 16(-4.44,-12.5) 17(-3.17,-12.5) 18(-1.9,-12.5) 19(-0.63,-12.5) 20(0.64,-12.5) 21(1.91,-12.5) 22(3.18,-12.5) 23(4.45,-12.5) 24(5.72,-12.5)
  rect 0.9x0.9 smd paste+0 mask+0: 39(-2.9,-3.86) 39(-2.9,-2.46) 39(-2.9,-1.06) 39(-1.5,-3.86) 39(-1.5,-2.46) 39(-1.5,-1.06) 39(-0.1,-3.86) 39(-0.1,-2.46) 39(-0.1,-1.06)
  Keep-Out Layer region: -9,6.205 9,6.205 9,12.395 -9,12.395
  Keep-Out Layer region: -9,6.205 9,6.205 9,12.395 -9,12.395
  silkscreen extent -10.2,-12.83 9.08,12.83, body extent -9.6,-13.35 9.6,12.93, height 0.25
FP-SOT25-IPC_A [mm]
  rect 1.707x0.616 smd paste+0 mask+0: 1(-1.201,0.95)
  rrect100% 1.707x0.616 smd paste+0 mask+0: 2(-1.201,0) 3(-1.201,-0.95) 4(1.201,-0.95) 5(1.201,0.95)
  silkscreen extent -3.08,-1.75 1.4,1.75, body extent -2.55,-2 2.55,2, height 0.25
FUSE_0154010.DRL [mil]
  rect 167x150 smd: 1(-125.5,0) 2(125.5,0)
  silkscreen extent -236,-99 192,99, body extent -192,-99 192,99, height 150
GCT_USB4105-GF-A [mm]
  rect 0.6x1.15 smd mask+0.05: A1_B12(-3.2,4.755) A4_B9(-2.4,4.755) B1_A12(3.2,4.755) B4_A9(2.4,4.755)
  rect 0.3x1.15 smd mask+0.05: A5(-1.25,4.755) A6(-0.25,4.755) A7(0.25,4.755) A8(1.25,4.755) B5(1.75,4.755) B6(0.75,4.755) B7(-0.75,4.755) B8(-1.75,4.755)
  oval 1x2.1 hole 0.6 slot 1.7 at 90 deg: SH1(-4.32,4.18) SH2(4.32,4.18)
  oval 1x1.8 hole 0.6 slot 1.4 at 90 deg: SH3(-4.32,0) SH4(4.32,0)
  round 0.65 hole 0.65 unplated: ""(-2.89,3.68) ""(2.89,3.68)
  silkscreen extent -4.47,-2.6 4.47,6.1
JST_B4B-XH-A(LF)(SN) [mm]
  rect 1.508x1.508 / inner round 1.508 / far side rect 1.508x1.508 hole 1: 1(3.75,-0.525)
  round 1.508 hole 1: 2(1.25,-0.525) 3(-1.25,-0.525) 4(-3.75,-0.525)
  silkscreen extent -6.2,-2.88 7.1,2.87, body extent -6.2,-2.88 6.2,2.88, height 7
OMRON-B3F-1000-4_V [mm] "TH, 4-Leads, Body 6x6mm"
  rect 1.5x1.5 hole 1 paste-2539.97: 1(-3.25,2.25)
  round 1.5 hole 1 paste-2539.97: 2(3.25,2.25) 4(3.25,-2.25)
  round 1.5 hole 1 paste-2539.97 mask+0.102: 3(-3.25,-2.25)
  silkscreen extent -4.67,-3 3,3, body extent -3.4,-3 3.4,3, height 4.5
PHOE-1803277_V [mm] "CONN, Body 9.2x9.01mm, Pitch 3.81mm"
  rect 1.7x1.7 hole 1.2: 1(-1.905,0)
  round 1.7 hole 1.2: 2(1.905,0)
  silkscreen extent -4.5,-8 4.51,2.02, body extent -4.51,-8 4.5,1.3, height 7.25
RESC1005X40 [mm]
  rect 0.7x0.9 smd: 1(-0.65,0) 2(0.65,0)
  body extent -0.5,-0.25 0.5,0.25, height 0.4
RESC1005X40N [mm]
  rect 0.49x0.6 smd paste+0 mask+0.102: 1(-0.455,0) 2(0.455,0)
  body extent -0.5,-0.25 0.5,0.25, height 0.4
S175146R [mm]
  rect 3.45x1.85 smd: 1(0,0)
  silkscreen extent 2.2,0 2.4,0.2
SOIC127P600X175-8N [mm]
  rect 1.525x0.65 smd: 1(-2.712,1.905) 2(-2.712,0.635) 3(-2.712,-0.635) 4(-2.712,-1.905) 5(2.712,-1.905) 6(2.712,-0.635) 7(2.712,0.635) 8(2.712,1.905)
  silkscreen extent -3.47,-2.45 1.6,2.58
SOIC127P600X175-14N [mm]
  rrect50% 1.97x0.6 smd paste+0 mask+0.102: 1(-2.475,3.81) 2(-2.475,2.54) 3(-2.475,1.27) 4(-2.475,0) 5(-2.475,-1.27) 6(-2.475,-2.54) 7(-2.475,-3.81) 8(2.475,-3.81) 9(2.475,-2.54) 10(2.475,-1.27) 11(2.475,0) 12(2.475,1.27) 13(2.475,2.54) 14(2.475,3.81)
  silkscreen extent -4.15,-4.32 1.17,4.32, body extent -3,-4.33 3,4.33, height 1.75
SOIC127P600X180-16N [mm]
  rrect25% 1.31x0.62 smd: 1(-2.75,4.445) 2(-2.75,3.175) 3(-2.75,1.905) 4(-2.75,0.635) 5(-2.75,-0.635) 6(-2.75,-1.905) 7(-2.75,-3.175) 8(-2.75,-4.445) 9(2.75,-4.445) 10(2.75,-3.175) 11(2.75,-1.905) 12(2.75,-0.635) 13(2.75,0.635) 14(2.75,1.905) 15(2.75,3.175) 16(2.75,4.445)
  silkscreen extent -2.85,-5 1.78,5.85, body extent -3,-5 3,5, height 1.8
SOT95P280X125-3N [mm]
  rrect50% 1.21x0.59 smd: 1(-1.255,0.95) 2(-1.255,-0.95) 3(1.255,0)
  silkscreen extent -2.41,-1.55 0.9,1.55, body extent -1.4,-1.45 1.4,1.45, height 1.25
SOT95P280X145-6N [mm]
  rrect25% 1.21x0.59 smd: 1(-1.255,0.95) 2(-1.255,0) 3(-1.255,-0.95) 4(1.255,-0.95) 5(1.255,0) 6(1.255,0.95)
  silkscreen extent -2.65,-1.56 0.81,1.56, body extent -1.4,-1.46 1.4,1.46, height 0.4
TOSH-SSOP-24_M [mm] "SOP, 24-Leads, Body 8x5.8mm, Pitch 0.65mm, IPC Low Density"
  oval 1.6x0.45 smd: 1(-3.7,3.575) 2(-3.7,2.925) 3(-3.7,2.275) 4(-3.7,1.625) 5(-3.7,0.975) 6(-3.7,0.325) 7(-3.7,-0.325) 8(-3.7,-0.975) 9(-3.7,-1.625) 10(-3.7,-2.275) 11(-3.7,-2.925) 12(-3.7,-3.575) 13(3.7,-3.575) 14(3.7,-2.925) 15(3.7,-2.275) 16(3.7,-1.625) 17(3.7,-0.975) 18(3.7,-0.325) 19(3.7,0.325) 20(3.7,0.975) 21(3.7,1.625) 22(3.7,2.275) 23(3.7,2.925) 24(3.7,3.575)
  silkscreen extent -3.82,-4 2.5,4.47, body extent -3.8,-4 3.8,4, height 1.6
VREG_LM5017MR/NOPB [mm]
  rrect5% 1.55x0.6 smd mask+0: 1(-2.7,1.905) 2(-2.7,0.635) 3(-2.7,-0.635) 4(-2.7,-1.905) 5(2.7,-1.905) 6(2.7,-0.635) 7(2.7,0.635) 8(2.7,1.905)
  round 0.6 hole 0.3: 9(-0.65,1.95) 9(-0.65,-0.65) 9(-0.65,0.65) 9(-0.65,-1.95) 9(0.65,1.95) 9(0.65,-0.65) 9(0.65,0.65) 9(0.65,-1.95)
  rect 2.95x4.9 smd paste-3 mask+0: 9(0,0)
  silkscreen extent -4.17,-2.52 1.95,2.52, body extent -3,-2.45 3,2.45, height 1.7
WE-LHMI_7050 [mm]
  rect 2.95x3.5 smd paste+0 mask+0.102: 1(-2.725,0) 2(2.725,0)
  Keep-Out Layer region: 1.25,-3.3 -1.25,-3.3 -1.25,3.3 1.25,3.3
  silkscreen extent -5.2,-3.4 3.4,3.4, body extent -3.65,-2.4 3.65,2.4, height 3.3
WURTH_61300421121 [mm]
  rect 1.875x1.875 / inner round 1.875 / far side rect 1.875x1.875 hole 1.25: 1(-1.27,-1.27)
  round 1.875 hole 1.25: 2(-1.27,1.27) 3(1.27,-1.27) 4(1.27,1.27)
  silkscreen extent -2.54,-3.31 2.54,2.54, body extent -2.54,-1.27 2.54,3.81, height 7.27

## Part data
C1: "470ÂµF 50V Aluminum Electrolytic Capacitors Radial, Can 10000 Hrs @ 105Â°C", Package="RADIAL-2 Panasonic"
C2 C4 C5 C11 C13 C15 C16 C20 C25 C33 C36 C37 C38: "0.1 ÂµF Â±10% 16V Ceramic Capacitor X7R 0402 (1005 Metric)", Package="SMD-2 Samsung"
C3 C6 C7 C8 C9 C10 C22 C23 C24 C27 C28 C29 C30 C31 C32 C35 J1: Package=None
C12: "Multilayer Ceramic Capacitors MLCC - SMD/SMT 1uF+/-10% 25V X5R 1005", Package="SMD-2 Samsung"
C14: "100F 50V Aluminum Electrolytic Capacitors Radial, Can 6000 Hrs @ 105C", Package="RADIAL-2 Panasonic"
C17 C18: "1000 pF Â±10% 50V Ceramic Capacitor X7R 0402 (1005 Metric)", Package="SMD-2 Samsung"
C19: "Cap Aluminum Lytic 470uF 16V 20% (8 X 11.5mm) Radial 3.5mm 950mA 6000h 105C Bulk", Package="RADIAL-2 Panasonic"
C21: "Tutup Aluminium Lytic 1000uF 16V 20% (10 X 16mm) Radial 5mm 1790mA 8000h 105C Massal", Package="RADIAL-2 Panasonic"
C26 C34: "4700 pF Â±10% 50V Ceramic Capacitor X7R 0402 (1005 Metric)", Package="SMD-2 Samsung"
D1 D2 D10 D11: library part CMP-2000-04943-2, "DIODE SCHOTTKY 40V 1A SMA", Forward Current=1A, Manufacturer="ON Semiconductor", Max Junction Temp=+125°C, Max Repetitive Reverse Voltage=40V, Max Surge Forward Current=40A, Package=403AE, Peak Reverse Current=0.2mA, Temperature="-65°C to +125°C", Temperature Range Low=-65°C
D3 D4: "5A, 60V, Schottky Rectifier", Package="SMB-2 Taiwan Semiconductor"
D5 D6 D7 D8 D9: "Green 571nm LED Indication - Discrete 2V 0603 (1608 Metric)", Package="0603 Lite-On Inc."
D12: "600W, 17.6V, 5%, Unidirectional, TVS", Package="SMD-2 Taiwan Semiconductor"
D13 D14: "Zener Diode 12V 5.3% 500mW SOD123", Package="SOD-123 Fairchild Semiconductor"
F1: "10 A 125 V AC 125 V DC Fuse Board Mount (Cartridge Style Excluded) Requires Holder, Surface Mount 2-SMD, Square End Block with Holder", Package="SMD-2 Littelfuse"
J2: library part CMP-17439-000167-1, "CONN HEADER VERT 6POS 2.5MM", Current Rating=3A, Flammability Rating="UL94 V-0", Insulation Color=Natural, Max Operating Temperature=85°C, Min Operating Temperature=-25°C, Voltage Rating=250V
J3 J7: library part CMP-17439-000014-3, "CONN HEADER VERT 3POS 2.5MM", Color=Natural, Contact Resistance=20mR, Current Rating=3A, Flammability Rating="UL94 V-0", Housing Color=White, Insulation Resistance=1GR, Max Operating Temperature=85°C, Max Voltage Rating (AC)=250V, Min Operating Temperature=-25°C
J4 J10 J11 J12 J14 J15: "Connector Header Through Hole 4 position 0.098 (2.50mm)", Package=None
J5 J8 J9 P2: library part CMP-002-00014-2, "Male Header, Pitch 3.81 mm, 1 x 2 Position, Height 7.25 mm, Tail Length 3.4 mm, RoHS, Bulk", Colour=Green, Current Rating=8A, Manufacturer="Phoenix Contact", Package Description="Male Header, Pitch 3.81 mm, 1 x 2 Position, Height 7.25 mm, Tail Length 3.4 mm", Package Quantity=50, Voltage Rating=160V
JP1: "Connector Header Through Hole 4 position 0.100 (2.54mm)", Package=None
L1 L2 L3: "4.7ÂµH Shielded Molded Inductor 5A 30.8mOhm Max Nonstandard", Package="Nonstandard WÃ¼rth Elektronik"
P1: "Socket, DC supply, male, PIN: 2", Package=Package
Q1 Q2 Q5: library part CMP-1670-00008-1, "NPN General Purpose Amplifier, 40 V, 0.2 A, -55 to 150 degC, 3-Pin SOT23, RoHS, Tape and Reel", Capacitance="1.8E-11 f", Frequency="12.288 MHz", Frequency Tolerance=30ppm, Load Capacitance="18 pF", Max Operating Temperature=70degC, Min Operating Temperature=-20degC, Package Quantity=1000
Q6: "N-Channel 30 V 5.8A (Ta) 1.4W (Ta) Surface Mount SOT-23", Package=None
Q7 Q8: "30V P-Channel MOSFET", Manufacturer_Name="Alpha & Omega Semiconductors"
R1 R3 R36 R43: "100 kOhms Â±1% 0.063W, 1/16W Chip Resistor 0402 (1005 Metric) Moisture Resistant Thick Film", Package="0402 Yageo"
R2 R44: "22 kOhms Â±1% 0.063W, 1/16W Chip Resistor 0402 (1005 Metric) Moisture Resistant Thick Film", Package="1005 Panasonic Electronic Components"
R4 R23: "54.9 kOhms Â±1% 0.063W, 1/16W Chip Resistor 0402 (1005 Metric) Moisture Resistant Thick Film", Package="1005 Panasonic Electronic Components"
R5 R6 R7 R10 R11 R12 R13 R14 R15 R20 R24 R34 R37 R41 R45: "10 kOhms Â±1% 0.063W, 1/16W Chip Resistor 0402 (1005 Metric) Moisture Resistant Thick Film", Package=Package
R8 R9: "5.1 kOhms Â±1% 0.063W, 1/16W Chip Resistor 0402 (1005 Metric) Moisture Resistant Thick Film", Package="1005 Panasonic Electronic Components"
R16: "220 Ohms Â±1% 0.063W, 1/16W Chip Resistor 0402 (1005 Metric) Moisture Resistant Thick Film", Package="1005 Panasonic Electronic Components"
R17 R18 R27 R40: "330 Ohms Â±1% 0.063W, 1/16W Chip Resistor 0402 (1005 Metric) Moisture Resistant Thick Film", Package="1005 Panasonic Electronic Components"
R19: "115 kOhms Â±1% 0.063W, 1/16W Chip Resistor 0402 (1005 Metric) Moisture Resistant Thick Film", Package="1005 Panasonic Electronic Components"
R21 R25: "200 kOhms Â±1% 0.063W, 1/16W Chip Resistor 0402 (1005 Metric) Moisture Resistant Thick Film", Package="1005 Panasonic Electronic Components"
R22 R26: "8.2 kOhms Â±1% 0.063W, 1/16W Chip Resistor 0402 (1005 Metric) Moisture Resistant Thick Film", Package="1005 Panasonic Electronic Components"
R28 R29 R30 R31 R33 R42: "1 kOhms Â±1% 0.063W, 1/16W Chip Resistor 0402 (1005 Metric) Moisture Resistant Thick Film", Package="0402-2 YAGEO"
R32 R38 R39: "4.7 kOhms Â±1% 0.063W, 1/16W Chip Resistor 0402 (1005 Metric) Moisture Resistant Thick Film", Package="1005 Panasonic Electronic Components"
R35: "100 Ohms Â±1% 0.063W, 1/16W Chip Resistor 0402 (1005 Metric) Moisture Resistant Thick Film", Package="0402 Yageo"
S1 S2 S3: library part CMP-011-00004-2, "Tactile Switch, SPST-NO, 0.05 A, 24 V, -25 to 70 degC, 4-Pin THD, RoHS, Bulk", Contact Current Rating=50mA, Manufacturer="Omron Electronic Components", Max Contact Resistance=100mohm, Max Operating Temperature=70°C, Max Voltage Rating (DC)=24V, Min Operating Temperature=-25°C, Operating Force=100gf, Package Description="4-Pin Through Hole Device, Body 6 x 6 mm", Package Quantity=1500, Resistance=0.1Ohm
TP1 TP2 TP3 TP4 TP5 TP6 TP7 TP8 TP9 TP10 TP11 TP12 TP13: "Hardware: SMT Test Point 1.63x3.25mm 2mm high (T+R)", Manufacturer_Name=Harwin, Mouser Part Number=855-S1751-46R
U1: library part CMP-04918-000464-1, "IC REG BUCK ADJ 5A TSOT23-6", Case/Package=SOT-23-6, Max Input Voltage=17V, Max Operating Temperature=125°C, Max Output Voltage=7V, Min Input Voltage=4.5V, Min Operating Temperature=-40°C, Min Output Voltage=600mV, Output Current=5A, Switching Frequency=500kHz
U2: library part CMP-12756-000035-1, "IC REG LINEAR 3.3V 600MA SOT25", Case/Package=SOT-23-5, Dropout Voltage=250mV, Max Input Voltage=6V, Max Operating Temperature=85°C, Max Output Current=600mA, Min Input Voltage=2.5V, Min Operating Temperature=-40°C, Output Voltage=3.3V, Package Quantity=1, Quiescent Current=55uA
U3: library part CMP-194065-000026-1, "RX TXRX MOD WIFI TRACE ANT SMD"
U4: "USB to serial chip CH340", Package=None
U5: library part CMP-1773-00001-1, "Driver IC for Dual DC Motor, 15 V, -20 to 85 degC, 24-Pin SSOP, RoHS, Tape and Reel", Case\Package=TO-236-3, Forward Current="70 mA", Forward Voltage="1 V", Max Operating Temperature="125 degC", Max Power Dissipation="200 mW", Max Surge Current="100 mA", Min Operating Temperature="-55 degC", Package Quantity=3000, Peak Reverse Current="0.1 uA"
U21 U22: "4.5-V to 60-V input, 5-A, step-down DC-DC converter with Eco-modeâ„¢", Package="HSOIC-8 Texas Instruments"
U23: "4-ch, 4.5-V to 5.5-V buffers with TTL-compatible CMOS inputs and 3-state outputs", Package="SOIC-14 Texas Instruments"
U24: "17V Clamp 5A (8/20Âµs) Ipp Tvs Diode Surface Mount SOT-23-6", Package="SOT-23-6 STMicroelectronics"

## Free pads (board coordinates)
  round 125.98 hole 125.98 unplated: M3(334.65,2460.63) M3(452.76,3779.53) M3(1141.73,846.46) M3(3129.92,2696.85) M3(3425.2,3562.99) M3(3779.53,157.48)

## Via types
v1: diameter 23.62, hole 11.81, Top Layer to Bottom Layer, tented both sides, 334 vias
v2: diameter 31.5, hole 15.75, Top Layer to Bottom Layer, tented both sides, 51 vias

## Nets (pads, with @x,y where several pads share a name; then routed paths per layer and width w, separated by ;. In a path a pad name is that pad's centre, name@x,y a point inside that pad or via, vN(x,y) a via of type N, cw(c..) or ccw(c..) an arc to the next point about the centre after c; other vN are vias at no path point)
5V_LOGIC: C8.1 D1.2 D2.2 U2.1 U2.3 | length 644.2
  Top Layer w31.5: D1.2@629.92,2781.5 D2.2@771.65,2781.5 851,2781.5 856.71,2775.79 C8.1@937.01,2775.79 937.01,2725.02 U2.1@936.99,2675.2 862.5,2675.2 850,2662.7 850,2612.89 862.5,2600.39 U2.3@936.99,2600.39
+3V3: C9.1 C10.1 C11.1 C13.1 C16.1 J2.2 J11.2 J12.2 J14.1 J15.4 R6.1 R7.1 R13.1 R14.1 R15.1 R29.1 R37.1 R38.1 R39.1 TP9.1 U2.5 U3.2 U4.4 U4.16 U5.20 | length 4252.9
  Top Layer w9.84: U5.20@838.58,2006.89 C16.1@912.13,2006.89
  Top Layer w19.68: J14.1@129.92,2751.97 129.92,2907.48 ; v1(192.91,2582.68) 188.98,2578.74 188.98,2383.86 242.13,2330.71
  Top Layer w23.62: U2.5@1031.52,2675.2 v1(1031.54,2707.01) ; v1(1102.95,2675.2) C9.1@1143.9,2675.2 ; v1(1102.95,2773.62) C10.1@1143.9,2773.62 ; TP9.1@1358.27,2657.48 v1(1414.37,2657.48) ; R37.1@1425.39,3110.24 v1(1425.39,3145.75) ; C11.1@1426.46,3562.99 v1(1458.15,3544.69) ; v1(1448.74,3188.98) R14.1@1482.09,3188.98 ; v1(1448.74,3818.9) R6.1@1482.09,3818.9 ; U3.2@1624.02,3562.6 v1(1673.23,3562.6) ; v1(1776.18,2708.98) R29.1@1811.02,2718.31 ; R7.1@2431.3,2962.6 v1(2464.65,2962.6) ; v1(2838.39,3147.05) U4.4@2883.86,3147.05 ; U4.16@3100.39,3297.05 v1(3100.39,3328.94) ; v1(3147.48,3297.24) C13.1@3181.81,3297.24 ; v1(3488.19,3779.53) R38.1@3521.65,3779.53 ; v1(3488.19,3858.27) R39.1@3521.65,3858.27
  Top Layer w31.5: J2.2@197.83,2116.14 250,2168.31 250,2316.54 ; C16.1@912.13,2007.87 912.13,2030.13 928,2046 946.05,2046 947.05,2047 R13.1@947.05,2078.74 1113.2,2078.74 1178,2143.54 1178,2560.54 v1(1031.54,2707.01) ; v1(1414.37,2657.48) 1414.37,2974.37 1432,2992 1462.5,2992 1482.09,3011.59 R15.1@1482.09,3031.5 ; v1(1425.39,3145.75) 1434,3154.35 1434,3174.24 v1(1448.74,3188.98)
  Bottom Layer w19.68: v1(192.91,2582.68) 192.91,2659.45 161.42,2690.94 171.26,2681.1 208.66,2681.1 ; 3631.89,3389.76 3631.89,3374.02 J12.2@3803.15,3202.76 ; 3637.8,3734.25 3781.5,3734.25 3793.31,3722.44
  Bottom Layer w31.5: 224.2,2675.2 v1(1102.95,2675.2)
  other v1: 3627.05,3401.57 3627.05,3740.16
+5V: C6.1 C7.1 C19.P C20.1 C36.1 D1.1 D10.2 J7.2 J8.1 L1.2 R4.1 R30.1 TP8.1 U23.10 U23.13 U23.14 | length 7373.4
  Top Layer w23.62: C7.1@1102.17,1909.45 v2(1146.26,1921.26) ; C20.1@1111.5,1732.28 1117.89,1708.39 v2(1121.85,1693.62) ; v2(1223.43,1702.68) L1.2@1223.43,1811.02 ; R4.1@1821.06,1694.88 v2(1858.35,1694.88) ; D10.2@3208.66,1954.72 v2(3265.94,1970.08) ; v2(3259.37,2233.46) U23.10@3325.79,2233.46 ; U23.13@3325.79,2383.46 v2(3392.2,2383.46) ; v2(3409.65,2272.91) C36.1@3420,2234.25
  Top Layer w31.5: D1.1@629.92,2612.2 629.92,1776.11 712.03,1694 1103.5,1694 1117.89,1708.39 1121.85,1712.35 ; C7.1@1102.17,1909.45 C6.1@1102.17,1811.02 1102.17,1763 1121.85,1743.32 ; v2(1121.85,1693.62) 1121.85,1712.35 ; v2(1146.26,1921.26) 1146.26,1740.74 1203.87,1683.13 ; C19.P@1171.26,1397.64 1171.26,1650.51 1203.87,1683.13 ; v2(1223.43,1655) v2@1223.43,1663.57 ; TP8.1@1614.17,1299.21 1614.17,1490.83 1558,1547 1340,1547 v2@1223.43,1663.57 ; v2(1858.35,1694.88) 1928,1764.54 1928,2166 1620,2474 1620,2768.5 1637.5,2786 1844.81,2786 1912.5,2718.31 R30.1@1929.13,2718.31 ; U23.14@3325.79,2433.46 3375,2433.46 3392.2,2416.26 v2(3392.2,2383.46) ; 1121.85,1712.35 1121.85,1743.32 ; 1121.85,1712.35 1122,1712.5 1122,1743.17 1121.85,1743.32 ; 1203.87,1683.13 v2@1223.43,1663.57 ; 1203.87,1683.13 v2(1223.43,1702.68) v2@1223.43,1663.57
  Bottom Layer w31.5: v2(1223.43,1655) 1360.43,1518 2813.87,1518 v2(3265.94,1970.08)
+5V_SERVO: C21.P C29.1 C30.1 C31.1 J3.2 L3.2 R23.1 R31.1 TP10.1 | length 5000.6
  Top Layer w19.68: R31.1@2047.24,2718.31 2055.12,2708.66 v1(2090.55,2708.66) ; R23.1@3539.37,700.98 3527.56,708.66 3657.48,838.58 3748.03,838.58 J3.2@3778.54,846.46
  Top Layer w59.06: TP10.1@3314.96,1082.68 3314.96,1172.96 v2(3390,1248)
  Bottom Layer w19.68: v1(2090.55,2708.66) 2586.61,2708.66 3377.95,1917.32 3377.95,1275.59 v2(3390,1248)
  Bottom Layer w59.06: v2(3031.5,645.67) 3031.5,889.5 3086.88,944.88 v2(3390,1248)
  Bottom Layer w78.74: C21.P@2952.76,1161.42 2952.76,944.88 ; v2(2992.13,645.67) 2952.76,685.04 2952.76,944.88 ; J3.2@3778.54,846.46 3720.47,846.46 3622.05,944.88 3086.88,944.88 2952.76,944.88
+VJET: C22.1 C23.1 C28.1 J5.1 L2.2 R19.1 R32.1 TP11.1 | length 2739.1
  Top Layer w19.68: 2047.24,941.42 2074.8,929.13 2476.38,929.13 2539.37,866.14 2539.37,724.41 R19.1@2515.75,700.79 ; TP11.1@2047.24,1082.68 2062.99,1149.61 v1(2062.99,1555.12) ; R32.1@2165.35,2710.63 2181.1,2704.72 2204.72,2681.1 v1(2204.72,2122.05)
  Top Layer w59.06: L2.2@2010.83,763.78 2010.83,905 2047.24,941.42 TP11.1@2047.24,1082.68
  Bottom Layer w19.68: v1(2062.99,1555.12) 2062.99,1980.32 v1(2204.72,2122.05)
AR_EN: JP1.1 Q1.3 | length 1348.8
  Top Layer w9.84: v1(3041,3065) 3041,3316 3116,3391 3351,3391 3371,3371 3371,3267.72 Q1.3@3370.08,3267.72
  Bottom Layer w9.84: JP1.1@2548.43,2981.5 2581,2948.92 2581,2914.07 2606.07,2889 2865,2889 v1(3041,3065)
AR_IO0: JP1.3 Q2.3 | length 882.7
  Top Layer w9.84: JP1.3@2648.43,2981.5 2719.92,2910 3321,2910 3336,2925 3336,3050.18 Q2.3@3370.08,3051.18
BUZ_B: Q5.1 R33.2 R34.1 | length 328.5
  Top Layer w9.84: R34.1@3073.03,1907.48 R33.2@3073.03,1848.43 Q5.1@3342.52,1848.43
BUZ_N: D10.1 J8.2 Q5.3 | length 405.8
  Top Layer w9.84: D10.1@3208.66,1785.43 3265.43,1785.43 3291.02,1811.02 Q5.3@3429.13,1811.02 3513,1811.02 3516.74,1807.28 J8.2@3602.36,1807.28
BUZZER: R33.1 U3.16 | length 1823.1
  Top Layer w9.84: v1(1793.7,2854.3) U3.16@1793.7,2913.39 ; v1(2156,2834) 2227.2,2834 2750,2311.2 2748.03,2305.12 v1(2748.03,2137.8) ; v1(3005.91,1879.92) 3025.59,1860.24 R33.1@3037.2,1848.43
  Bottom Layer w9.84: v1(1793.7,2854.3) 1814,2834 v1(2156,2834) ; v1(2748.03,2137.8) v1(3005.91,1879.92)
COMP_SERVO: C35.1 R26.1 U22.6 | length 153.8
  Top Layer w9.84: C35.1@3411.42,666.06 3440,666.06 3440.91,665.16 R26.1@3470.47,665.16 3470.47,631.09 3489.57,612 U22.6@3489.57,578.74
COMP_VJET: C27.1 R22.1 U21.6 | length 153.8
  Top Layer w9.84: C27.1@2387.8,666.06 2416,666.06 2416.91,665.16 R22.1@2446.85,665.16 2446.85,631.09 2465.94,612 U21.6@2465.94,578.74
DTR: Q2.2 R10.1 U4.13 | length 532.7
  Top Layer w7.87: R10.1@3171.06,3364.17 3173.23,3350.39 v1(3173.23,3330.71)
  Top Layer w9.84: U4.13@3100.39,3147.05 3143,3147.05 3144,3146.05 3144,3032.28 3162.5,3013.78 Q2.2@3283.46,3013.78
  Bottom Layer w7.87: v1(3141.73,3149.61) 3173.23,3181.1 v1(3173.23,3330.71)
EN_BUCK: R3.2 U1.5 | length 129.3
  Top Layer w9.84: U1.5@1696.86,1811.02 1786.38,1811.02 1787.4,1810 R3.2@1787.4,1771.65
ENC_A: C17.1 J2.4 R14.2 TP3.1 U3.6 | length 3661
  Top Layer w9.84: TP3.1@413.39,1523.62 413.39,1523 171.5,1523 157,1537.5 157,1647.13 139.76,1664.37 139.76,1861.22 J2.4@197.83,1919.29 157,1960.13 157,2053 175,2071 218,2071 483.88,2336.88 483.88,3000.38 862.5,3379 1227.5,3379 1244,3362.5 1244,3194.5 1262.5,3176 1378,3176 1422,3220 1500,3220 1517.91,3202.09 ; C17.1@1517.01,3110.24 1517.01,3149 1517.91,3149.91 R14.2@1517.91,3188.98 1517.91,3202.09 ; U3.6@1624.02,3362.6 1571.6,3362.6 1559,3350 1559,3261.41 1517.91,3220.33 1517.91,3202.09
